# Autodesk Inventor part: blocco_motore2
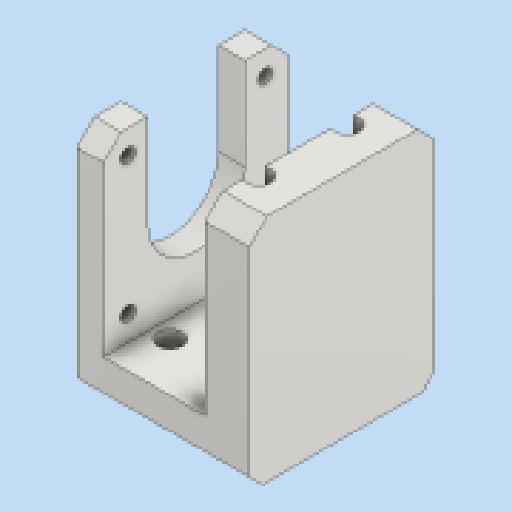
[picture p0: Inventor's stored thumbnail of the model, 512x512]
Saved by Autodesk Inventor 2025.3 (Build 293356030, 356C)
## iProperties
Created: 2025-11
Part Number: blocco_motore2
Material: Plastica ABS
Document SubType Name: Modeling
Designer: R5800u
Density: 1.06 g/cm^3
Appearance: Acciaio
Author: R5800u
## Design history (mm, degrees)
sketch "Schizzo1"
  geometry: L1 (0, 0)-(-15, 0); L2 (-15, 0)-(-15, 52); L3 (-15, 52)-(0, 52); L4 (0, 52)-(0, 0); L5 (-15, 0)-(-47, 0); L6 (-47, 0)-(-47, 10); L7 (-47, 10)-(-15, 10); L8 (-15, 10)-(-15, 0); 1 further point
  constraints: 16 end point, 4 parallel, 2 horizontal, 2 perpendicular
  dimensions: "d0" = 15 distance of L2.end L3.end; "d1" = 52 distance of L1.end L2.end; "d2" = 32 distance of L6.end L7.end; "d3" = 10 distance of L5.end L6.end
extrude "Estrusione1" new body sketch "Schizzo1" stored distance "d4" = 42; taper "d5" = 0 deg
sketch "Schizzo2"
  geometry: L1 (0, 42)-(0, 0) reference; L2 (0, 21)-(32, 21); L3 (32, 42)-(32, 0) reference; C1 r 1.25 at (26.1, 31); C2 r 1.25 at (26.1, 11); C3 r 1.25 at (6.1, 11); C4 r 1.25 at (6.1, 31); 1 further point
  constraints: 4 centre point, 2 end point, 2 midpoint, 1 other
  dimensions: "d31" = 20 distance of C4.centre C3.centre; "d32" = 20 distance of C1.centre C2.centre; "d33" = 20 distance of C2.centre C3.centre; "d34" = 20 distance of C1.centre C4.centre; "d35" = 6.1 distance from line of L1 C3.centre
hole "Foro1" sketch "Schizzo2" at (6.1, 31), (6.1, 11), (26.1, 11), (26.1, 31) diameter "d9" = 2.9; stored, may be unused: countersink angle "d13" = 90 deg, drill point angle "d15" = 118 deg; dims "d10" = 6, "d11" = 5.5, "d12" = 2.9, "d14" = 8
sketch "Schizzo3"
  geometry: C1 r 1.45 at (6.1, 11) reference; C2 r 1.45 at (6.1, 31) reference; C3 r 1.45 at (26.1, 11) reference; C4 r 1.45 at (26.1, 31) reference; 5 further points
  constraints: 4 coincident
hole "Foro2" sketch "Schizzo3" at (6.1, 11), (6.1, 31), (26.1, 11), (26.1, 31) diameter "d16" = 2.9; stored, may be unused: countersink angle "d20" = 90 deg, drill point angle "d22" = 118 deg; dims "d17" = 6, "d18" = 5.5, "d19" = 3.5, "d21" = 8
sketch "Schizzo4"
  geometry: C1 r 1.5 at (10, 15.05) reference; C2 r 1.5 at (17, 8.05) reference; C3 r 1.5 at (17, 22.05) reference; C4 r 1.5 at (24, 15.05) reference; 1 further point
hole "Foro3" sketch "Schizzo4" at (10, 15.05), (17, 8.05), (24, 15.05), (17, 22.05) diameter "d23" = 3.4; stored, may be unused: countersink angle "d27" = 90 deg, drill point angle "d29" = 118 deg; dims "d24" = 6, "d25" = 6.5, "d26" = 3.4, "d28" = 8
sketch "Schizzo5"
  geometry: L1 (0, 0)-(-42, 0) reference; L2 (0, 10)-(0, 0) reference; L3 (-42, 10)-(0, 10) reference; L4 (-42, 0)-(-42, 10) reference; 1 further point
extrude "Estrusione2" join sketch "Schizzo5" distance "d36" = 4; taper "d37" = 0 deg
sketch "Schizzo6"
  geometry: L1 (-36, 0)-(-36, 42) reference; L2 (0, 42)-(0, 0) reference; L3 (0, 0)-(-36, 0) reference; L4 (0, 42)-(-36, 42) reference; L5 (-36, 0)-(-30, 0); L6 (-30, 0)-(-30, 42); L7 (-30, 42)-(-36, 42); L8 (-36, 42)-(-36, 0); L9 (0, 42)-(-36, 42) reference; L10 (0, 0)-(-7, 0); L11 (-7, 0)-(-7, 42); L12 (-7, 42)-(0, 42); L13 (0, 42)-(0, 0); 4 further points
  constraints: 16 end point, 4 parallel, 2 horizontal, 2 perpendicular, 2 point on line
extrude "Estrusione3" join sketch "Schizzo6" distance "d38" = 42; taper "d39" = 0 deg
sketch "Schizzo7"
  geometry: C1 r 1.45 at (24.1, -31) reference; C2 r 2.75 at (24.1, -31); C3 r 2.75 at (24.1, -11); A1 r 2.75 centre (24.1, -31) between (23, -28.48) and (23, -33.52) reference; A2 r 2.75 centre (24.1, -11) between (23, -8.48) and (23, -13.52) reference; A3 r 2.75 centre (24.1, -11) between (23, -13.52) and (23, -8.48) reference; 3 further points
  constraints: 2 centre point, 2 coincident, 1 concentric
extrude "Estrusione4" cut sketch "Schizzo7" distance "d40" = 42; taper "d41" = 0 deg
sketch "Schizzo8"
  geometry: L1 (0, 52)-(-42, 52) reference; L2 (-10, 31.15)-(-32, 31.15); L3 (-32, 31.15)-(-32, 52); L4 (-32, 52)-(-10, 52); L5 (-10, 52)-(-10, 31.15); 4 further points
  constraints: 8 end point, 2 parallel, 1 horizontal, 1 perpendicular, 1 point on line, 2 other
extrude "Estrusione5" cut sketch "Schizzo8" stored distance "d42" = 42; taper "d43" = 0 deg
sketch "Schizzo9"
  geometry: L1 (-32, 31.15)-(-32, 52) reference; L2 (-42, 52)-(-32, 52) reference; L3 (-42, 0)-(-42, 52) reference; L4 (-42, 0)-(0, 0) reference; L5 (0, 0)-(0, 52) reference; L6 (-10, 52)-(0, 52) reference; L7 (-10, 52)-(-10, 31.15) reference; A1 r 11 centre (-21, 31.15) between (-32, 31.15) and (-10, 31.15) reference; 1 further point
extrude "Estrusione6" join sketch "Schizzo9" distance "d44" = 4; taper "d45" = 0 deg
sketch "Schizzo10"
  geometry: L1 (0, 0)-(0, 52) reference; L2 (42, 0)-(0, 0) reference; L3 (42, 0)-(42, 52) reference; L4 (0, 52)-(42, 52) reference; 1 further point
extrude "Estrusione7" join sketch "Schizzo10" distance "d46" = 3; taper "d47" = 0 deg
chamfer "Smusso2" distance "d48" = 4; stored, may be unused: second distance "d49" = 2, angle "d50" = 45 deg
sketch "Schizzo11"
  geometry: C1 r 1.25 at (-5.5, 46.65) reference; C2 r 1.25 at (-36.5, 46.65) reference; C3 r 1.25 at (-36.5, 15.65) reference; C4 r 1.25 at (-5.5, 15.65) reference; 1 further point
hole "Foro4" sketch "Schizzo11" at (-5.5, 15.65), (-5.5, 46.65), (-36.5, 46.65), (-36.5, 15.65) diameter "d51" = 3.2; stored, may be unused: countersink angle "d55" = 90 deg, drill point angle "d57" = 118 deg; dims "d52" = 6, "d53" = 6, "d54" = 1.5, "d56" = 12
chamfer "Smusso3" distance "d58" = 3; stored, may be unused: second distance "d59" = 2, angle "d60" = 45 deg
node "Solido1"
node "Riferimento5"
node "Riferimento6"
node "Riferimento7"
node "Riferimento8"
node "Linea chiusa proiettata1"
node "Riferimento10"
node "Linea chiusa proiettata2"
node "Linea chiusa proiettata3"
node "Riferimento11"
node "Riferimento12"
node "Riferimento13"
node "Riferimento14"
